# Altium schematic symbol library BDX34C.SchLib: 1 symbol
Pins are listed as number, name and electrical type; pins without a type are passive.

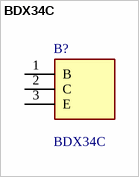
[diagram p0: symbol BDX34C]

## BDX34C
designator B?
BDX34C, Darlington Transistor, PNP 10 A 100 V HFE:750, 3-Pin, TO-220; Manufacturer_Name: STMicroelectronics; Geometry.Height: 4.6mm
footprint TO270P460X1020X2008-3P
pins: 1 B, 2 C, 3 E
